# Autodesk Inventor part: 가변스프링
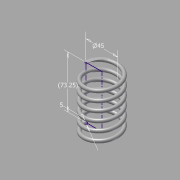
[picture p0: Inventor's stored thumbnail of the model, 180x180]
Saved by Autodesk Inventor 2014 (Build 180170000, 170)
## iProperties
Created: 2015-10
Part Number: 가변스프링
Material: 강철, 연강
Document SubType Name: Modeling
Designer: youjin12
Mass: 129.009 g
Surface Area: 133.045 cm^2
Volume: 16.4133 cm^3
Density: 7.86 g/cm^3
Appearance: 강철
Author: youjin12
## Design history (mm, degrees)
sketch "스케치2"
  geometry: L1 (0, 0)-(22.5, 0); L2 (22.5, 0)-(22.5, 73.25); L3 (22.5, 73.25)-(0, 73.25); L4 (0, 73.25)-(0, 0); C1 r 2.5 at (22.5, 0); 1 further point
  constraints: 8 end point, 2 coincident, 2 parallel, 1 centre point, 1 horizontal, 1 perpendicular
  dimensions: "d0" = 45 diameter of L2 L4; "d1" = 73.25 distance between parallel lines of L1 L3 (derived); "d2" = 5 diameter of C1
feature "코일1" sketch "스케치2" pitch "d3" = 10; turns "d5" = 6; dims "d4" = 73.25 (= d1), "d6" = 0, angle "d7" = 90 deg, angle "d8" = 90 deg, "d9" = 0, "d10" = 0
sketch "스케치3"
  geometry: L1 (-25, 0)-(-20, 0) reference; 1 further point
  constraints: 1 horizontal alignment
extrude "돌출1" cut sketch "스케치3" stored distance "d11" = 10; taper "d12" = 0 deg
node "작업 평면1"
sketch "스케치4"
  geometry: L1 (-20, 0)-(-25, 0) reference; 1 further point
  constraints: 1 horizontal alignment
extrude "돌출2" cut sketch "스케치4" stored distance "d13" = 10; taper "d14" = 0 deg
node "솔리드1"
node "절단 모서리 투영1"
node "절단 모서리 투영2"
